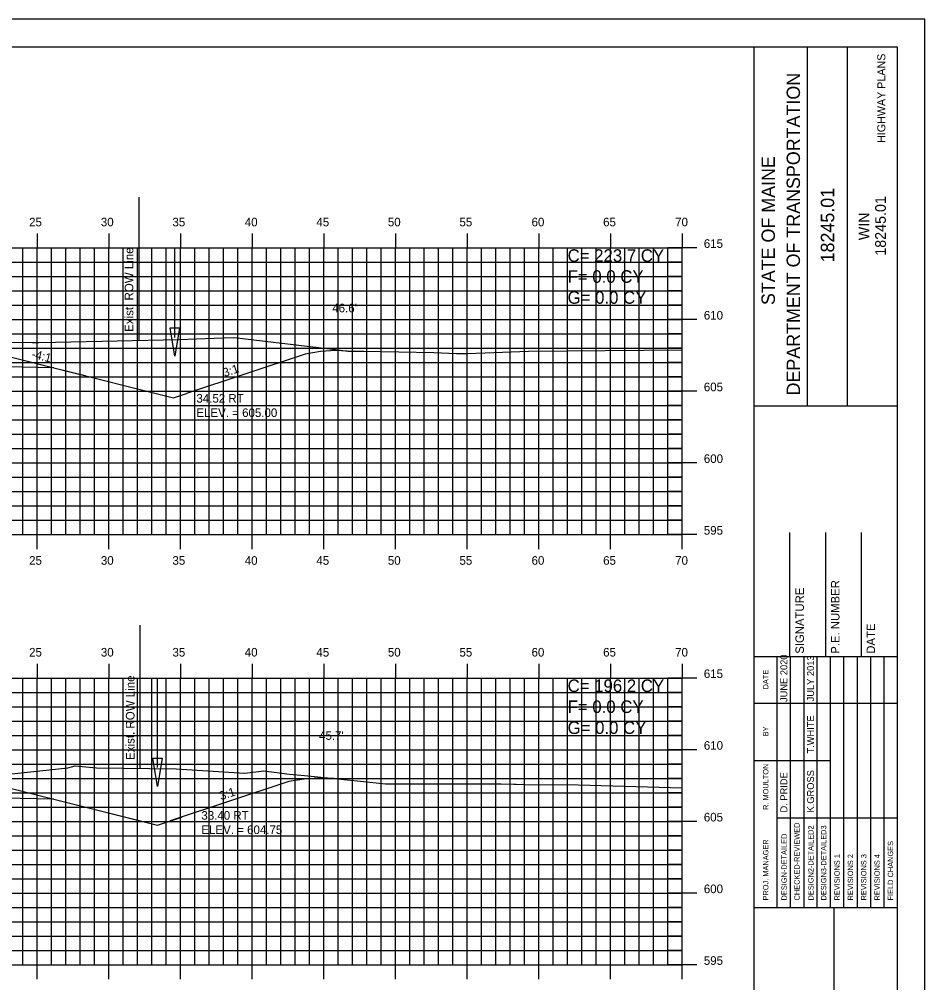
# Model space of a CAD drawing. Extents: x 1070760 to 1070930, y 779716 to 779826.
# Drawn here: x 1070866.6 to 1070929.8, y 779758.5 to 779825.6 of the extents above; entities that cross this region are included whole.
import ezdxf

# ---------------------------------------------------------------- set-up
doc = ezdxf.new("R2010")
doc.units = 0
for name, color, linetype in [('ANNOTATION', 7, 'Continuous'), ('BORDER', 7, 'Continuous'), ('D_Drainage_Ditch_Line', 7, 'Continuous'), ('D_Roadway_Centerline', 7, 'Continuous'), ('D_Roadway_Drive_SubGrade', 7, 'Continuous'), ('D_Roadway_SlopeLines', 7, 'Continuous'), ('D_Roadway_SubGrade', 7, 'Continuous'), ('D_Text_Standard', 7, 'Continuous'), ('E_ROW_Line', 7, 'Continuous'), ('H_V ANNOTATION', 7, 'Continuous'), ('HIGHWAY_TITLE', 7, 'Continuous'), ('MAJOR', 7, 'Continuous'), ('MINOR', 7, 'Continuous'), ('PLOT BOUNDARY', 7, 'Continuous'), ('S_Roadway_Centerline', 7, 'Continuous')]:
    doc.layers.add(name, color=color, linetype=linetype)

msp = doc.modelspace()

# ---------------------------------------------------------------- linework, layer by layer
at = {"layer": 'BORDER'}
for p, q in [((1070917.881, 779718.706), (1070917.881, 779823.706)), ((1070921.609, 779798.703), (1070921.609, 779823.703)), ((1070924.404, 779798.703), (1070924.404, 779823.703)), ((1070917.882, 779798.7), (1070927.881, 779798.7)), ((1070920.381, 779781.209), (1070920.381, 779789.856)), ((1070922.881, 779781.209), (1070922.881, 779789.856)), ((1070925.381, 779781.209), (1070925.381, 779789.856)), ((1070917.881, 779781.209), (1070927.881, 779781.209)), ((1070917.881, 779763.709), (1070927.881, 779763.709)), ((1070923.472, 779728.709), (1070923.472, 779763.709))]:
    msp.add_line(p, q, dxfattribs=at)
msp.add_lwpolyline([(1070767.881, 779718.706), (1070927.881, 779718.706), (1070927.881, 779823.706), (1070767.881, 779823.706)], close=True, dxfattribs=at)
for points in [[(1070919.496, 779777.959), (1070919.496, 779781.209)], [(1070920.428, 779763.712), (1070920.428, 779781.209)], [(1070921.36, 779781.209), (1070921.36, 779763.712)], [(1070922.292, 779763.712), (1070922.292, 779781.209)], [(1070923.223, 779763.712), (1070923.223, 779781.209)], [(1070924.155, 779763.712), (1070924.155, 779781.209)], [(1070925.087, 779763.712), (1070925.087, 779781.209)], [(1070926.018, 779763.712), (1070926.018, 779781.209)], [(1070926.95, 779763.712), (1070926.95, 779781.209)], [(1070919.497, 779763.712), (1070919.497, 779780.503)], [(1070917.881, 779777.959), (1070927.881, 779777.959)], [(1070917.881, 779773.959), (1070919.497, 779773.959)], [(1070919.496, 779773.959), (1070923.222, 779773.959)], [(1070919.496, 779769.959), (1070927.881, 779769.959)]]:
    msp.add_lwpolyline(points, dxfattribs=at)
at = {"layer": 'D_Drainage_Ditch_Line'}
for p, q in [((1070877.484, 779803.462), (1070877.485, 779809.706)), ((1070876.282, 779773.462), (1070876.283, 779779.706))]:
    msp.add_line(p, q, dxfattribs=at)
for points in [[(1070877.156, 779804.118), (1070877.812, 779804.118), (1070877.484, 779802.15)], [(1070875.954, 779774.118), (1070876.61, 779774.118), (1070876.282, 779772.15)]]:
    msp.add_lwpolyline(points, close=True, dxfattribs=at)
at = {"layer": 'D_Roadway_Centerline'}
for points in [[(1070889.505, 779802.511), (1070888.699, 779802.539), (1070887.647, 779802.467), (1070886.589, 779802.291), (1070878.304, 779799.553)], [(1070888.58, 779772.696), (1070887.556, 779772.732), (1070886.505, 779772.659), (1070885.447, 779772.483), (1070877.161, 779769.746)], [(1070869.04, 779771.266), (1070875.281, 779769.706)]]:
    msp.add_lwpolyline(points, dxfattribs=at)
at = {"layer": 'D_Roadway_Drive_SubGrade'}
for p, q in [((1070869.04, 779801.347), (1070877.404, 779799.256)), ((1070877.404, 779799.256), (1070878.304, 779799.553)), ((1070869.04, 779771.266), (1070876.283, 779769.456)), ((1070876.283, 779769.456), (1070877.977, 779770.016))]:
    msp.add_line(p, q, dxfattribs=at)
at = {"layer": 'D_Roadway_SlopeLines'}
for points in [[(1070869.04, 779801.347), (1070871.228, 779800.799)], [(1070869.04, 779771.266), (1070875.281, 779769.706)]]:
    msp.add_lwpolyline(points, dxfattribs=at)
at = {"layer": 'D_Roadway_SubGrade'}
for points in [[(1070854.881, 779802.213), (1070854.881, 779803.713), (1070854.881, 779803.713), (1070858.881, 779803.553), (1070858.881, 779803.886), (1070869.04, 779801.347), (1070854.881, 779801.63)], [(1070854.881, 779772.133), (1070854.881, 779773.633), (1070854.881, 779773.633), (1070858.881, 779773.473), (1070858.881, 779773.806), (1070869.04, 779771.266), (1070854.881, 779771.549)]]:
    msp.add_lwpolyline(points, close=True, dxfattribs=at)
at = {"layer": 'E_ROW_Line'}
for p, q in [((1070874.993, 779803.252), (1070874.993, 779813.252)), ((1070874.993, 779803.252), (1070874.993, 779813.252)), ((1070875.075, 779773.401), (1070875.075, 779783.401)), ((1070875.075, 779773.401), (1070875.075, 779783.401))]:
    msp.add_line(p, q, dxfattribs=at)
at = {"layer": 'MAJOR'}
for p, q in [((1070867.881, 779810.708), (1070867.881, 779809.706)), ((1070872.881, 779810.708), (1070872.881, 779809.706)), ((1070877.881, 779810.708), (1070877.881, 779809.706)), ((1070882.881, 779810.708), (1070882.881, 779809.706)), ((1070887.881, 779810.708), (1070887.881, 779809.706)), ((1070892.881, 779810.708), (1070892.881, 779809.706)), ((1070897.881, 779810.708), (1070897.881, 779809.706)), ((1070902.881, 779810.708), (1070902.881, 779809.706)), ((1070907.881, 779810.708), (1070907.881, 779809.706)), ((1070912.881, 779810.708), (1070912.881, 779809.706)), ((1070772.881, 779809.706), (1070912.881, 779809.706)), ((1070772.881, 779809.706), (1070912.881, 779809.706)), ((1070867.881, 779789.706), (1070867.881, 779809.706)), ((1070872.881, 779789.706), (1070872.881, 779809.706)), ((1070877.881, 779789.706), (1070877.881, 779809.706)), ((1070882.881, 779789.706), (1070882.881, 779809.706)), ((1070887.881, 779789.706), (1070887.881, 779809.706)), ((1070892.881, 779789.706), (1070892.881, 779809.706)), ((1070897.881, 779789.706), (1070897.881, 779809.706)), ((1070902.881, 779789.706), (1070902.881, 779809.706)), ((1070907.881, 779789.706), (1070907.881, 779809.706)), ((1070913.883, 779809.706), (1070911.879, 779809.706)), ((1070912.881, 779789.706), (1070912.881, 779809.706)), ((1070912.881, 779789.706), (1070912.881, 779809.706)), ((1070772.881, 779804.706), (1070912.881, 779804.706)), ((1070913.883, 779804.706), (1070911.879, 779804.706)), ((1070772.881, 779799.706), (1070912.881, 779799.706)), ((1070913.883, 779799.706), (1070911.879, 779799.706)), ((1070772.881, 779794.706), (1070912.881, 779794.706)), ((1070913.883, 779794.706), (1070911.879, 779794.706)), ((1070772.881, 779789.706), (1070912.881, 779789.706)), ((1070772.881, 779789.706), (1070912.881, 779789.706)), ((1070867.881, 779788.704), (1070867.881, 779789.706)), ((1070872.881, 779788.704), (1070872.881, 779789.706)), ((1070877.881, 779788.704), (1070877.881, 779789.706)), ((1070882.881, 779788.704), (1070882.881, 779789.706)), ((1070887.881, 779788.704), (1070887.881, 779789.706)), ((1070892.881, 779788.704), (1070892.881, 779789.706)), ((1070897.881, 779788.704), (1070897.881, 779789.706)), ((1070902.881, 779788.704), (1070902.881, 779789.706)), ((1070907.881, 779788.704), (1070907.881, 779789.706)), ((1070913.883, 779789.706), (1070911.879, 779789.706)), ((1070912.881, 779788.704), (1070912.881, 779789.706)), ((1070867.881, 779780.708), (1070867.881, 779779.706)), ((1070872.881, 779780.708), (1070872.881, 779779.706)), ((1070877.881, 779780.708), (1070877.881, 779779.706)), ((1070882.881, 779780.708), (1070882.881, 779779.706)), ((1070887.881, 779780.708), (1070887.881, 779779.706)), ((1070892.881, 779780.708), (1070892.881, 779779.706)), ((1070897.881, 779780.708), (1070897.881, 779779.706)), ((1070902.881, 779780.708), (1070902.881, 779779.706)), ((1070907.881, 779780.708), (1070907.881, 779779.706)), ((1070912.881, 779780.708), (1070912.881, 779779.706)), ((1070772.881, 779779.706), (1070912.881, 779779.706)), ((1070772.881, 779779.706), (1070912.881, 779779.706)), ((1070867.881, 779759.706), (1070867.881, 779779.706)), ((1070872.881, 779759.706), (1070872.881, 779779.706)), ((1070877.881, 779759.706), (1070877.881, 779779.706)), ((1070882.881, 779759.706), (1070882.881, 779779.706)), ((1070887.881, 779759.706), (1070887.881, 779779.706)), ((1070892.881, 779759.706), (1070892.881, 779779.706)), ((1070897.881, 779759.706), (1070897.881, 779779.706)), ((1070902.881, 779759.706), (1070902.881, 779779.706)), ((1070907.881, 779759.706), (1070907.881, 779779.706)), ((1070913.883, 779779.706), (1070911.879, 779779.706)), ((1070912.881, 779759.706), (1070912.881, 779779.706)), ((1070912.881, 779759.706), (1070912.881, 779779.706)), ((1070772.881, 779774.706), (1070912.881, 779774.706)), ((1070913.883, 779774.706), (1070911.879, 779774.706)), ((1070772.881, 779769.706), (1070912.881, 779769.706)), ((1070913.883, 779769.706), (1070911.879, 779769.706)), ((1070772.881, 779764.706), (1070912.881, 779764.706)), ((1070913.883, 779764.706), (1070911.879, 779764.706)), ((1070772.881, 779759.706), (1070912.881, 779759.706)), ((1070772.881, 779759.706), (1070912.881, 779759.706)), ((1070867.881, 779758.704), (1070867.881, 779759.706)), ((1070872.881, 779758.704), (1070872.881, 779759.706)), ((1070877.881, 779758.704), (1070877.881, 779759.706)), ((1070882.881, 779758.704), (1070882.881, 779759.706)), ((1070887.881, 779758.704), (1070887.881, 779759.706)), ((1070892.881, 779758.704), (1070892.881, 779759.706)), ((1070897.881, 779758.704), (1070897.881, 779759.706)), ((1070902.881, 779758.704), (1070902.881, 779759.706)), ((1070907.881, 779758.704), (1070907.881, 779759.706)), ((1070913.883, 779759.706), (1070911.879, 779759.706)), ((1070912.881, 779758.704), (1070912.881, 779759.706))]:
    msp.add_line(p, q, dxfattribs=at)
at = {"layer": 'MINOR'}
for p, q in [((1070866.881, 779789.706), (1070866.881, 779809.706)), ((1070868.881, 779789.706), (1070868.881, 779809.706)), ((1070869.881, 779789.706), (1070869.881, 779809.706)), ((1070870.881, 779789.706), (1070870.881, 779809.706)), ((1070871.881, 779789.706), (1070871.881, 779809.706)), ((1070873.881, 779789.706), (1070873.881, 779809.706)), ((1070874.881, 779789.706), (1070874.881, 779809.706)), ((1070875.881, 779789.706), (1070875.881, 779809.706)), ((1070876.881, 779789.706), (1070876.881, 779809.706)), ((1070878.881, 779789.706), (1070878.881, 779809.706)), ((1070879.881, 779789.706), (1070879.881, 779809.706)), ((1070880.881, 779789.706), (1070880.881, 779809.706)), ((1070881.881, 779789.706), (1070881.881, 779809.706)), ((1070883.881, 779789.706), (1070883.881, 779809.706)), ((1070884.881, 779789.706), (1070884.881, 779809.706)), ((1070885.881, 779789.706), (1070885.881, 779809.706)), ((1070886.881, 779789.706), (1070886.881, 779809.706)), ((1070888.881, 779789.706), (1070888.881, 779809.706)), ((1070889.881, 779789.706), (1070889.881, 779809.706)), ((1070890.881, 779789.706), (1070890.881, 779809.706)), ((1070891.881, 779789.706), (1070891.881, 779809.706)), ((1070893.881, 779789.706), (1070893.881, 779809.706)), ((1070894.881, 779789.706), (1070894.881, 779809.706)), ((1070895.881, 779789.706), (1070895.881, 779809.706)), ((1070896.881, 779789.706), (1070896.881, 779809.706)), ((1070898.881, 779789.706), (1070898.881, 779809.706)), ((1070899.881, 779789.706), (1070899.881, 779809.706)), ((1070900.881, 779789.706), (1070900.881, 779809.706)), ((1070901.881, 779789.706), (1070901.881, 779809.706)), ((1070903.881, 779789.706), (1070903.881, 779809.706)), ((1070904.881, 779789.706), (1070904.881, 779809.706)), ((1070905.881, 779789.706), (1070905.881, 779809.706)), ((1070906.881, 779789.706), (1070906.881, 779809.706)), ((1070908.881, 779789.706), (1070908.881, 779809.706)), ((1070909.881, 779789.706), (1070909.881, 779809.706)), ((1070910.881, 779789.706), (1070910.881, 779809.706)), ((1070911.881, 779789.706), (1070911.881, 779809.706)), ((1070772.881, 779808.706), (1070912.881, 779808.706)), ((1070912.881, 779808.706), (1070911.879, 779808.706)), ((1070772.881, 779807.706), (1070912.881, 779807.706)), ((1070912.881, 779807.706), (1070911.879, 779807.706)), ((1070772.881, 779806.706), (1070912.881, 779806.706)), ((1070912.881, 779806.706), (1070911.879, 779806.706)), ((1070772.881, 779805.706), (1070912.881, 779805.706)), ((1070912.881, 779805.706), (1070911.879, 779805.706)), ((1070772.881, 779803.706), (1070912.881, 779803.706)), ((1070912.881, 779803.706), (1070911.879, 779803.706)), ((1070772.881, 779802.706), (1070912.881, 779802.706)), ((1070912.881, 779802.706), (1070911.879, 779802.706)), ((1070772.881, 779801.706), (1070912.881, 779801.706)), ((1070912.881, 779801.706), (1070911.879, 779801.706)), ((1070772.881, 779800.706), (1070912.881, 779800.706)), ((1070912.881, 779800.706), (1070911.879, 779800.706)), ((1070772.881, 779798.706), (1070912.881, 779798.706)), ((1070912.881, 779798.706), (1070911.879, 779798.706)), ((1070772.881, 779797.706), (1070912.881, 779797.706)), ((1070912.881, 779797.706), (1070911.879, 779797.706)), ((1070772.881, 779796.706), (1070912.881, 779796.706)), ((1070912.881, 779796.706), (1070911.879, 779796.706)), ((1070772.881, 779795.706), (1070912.881, 779795.706)), ((1070912.881, 779795.706), (1070911.879, 779795.706)), ((1070772.881, 779793.706), (1070912.881, 779793.706)), ((1070912.881, 779793.706), (1070911.879, 779793.706)), ((1070772.881, 779792.706), (1070912.881, 779792.706)), ((1070912.881, 779792.706), (1070911.879, 779792.706)), ((1070772.881, 779791.706), (1070912.881, 779791.706)), ((1070912.881, 779791.706), (1070911.879, 779791.706)), ((1070772.881, 779790.706), (1070912.881, 779790.706)), ((1070912.881, 779790.706), (1070911.879, 779790.706)), ((1070866.881, 779759.706), (1070866.881, 779779.706)), ((1070868.881, 779759.706), (1070868.881, 779779.706)), ((1070869.881, 779759.706), (1070869.881, 779779.706)), ((1070870.881, 779759.706), (1070870.881, 779779.706)), ((1070871.881, 779759.706), (1070871.881, 779779.706)), ((1070873.881, 779759.706), (1070873.881, 779779.706)), ((1070874.881, 779759.706), (1070874.881, 779779.706)), ((1070875.881, 779759.706), (1070875.881, 779779.706)), ((1070876.881, 779759.706), (1070876.881, 779779.706)), ((1070878.881, 779759.706), (1070878.881, 779779.706)), ((1070879.881, 779759.706), (1070879.881, 779779.706)), ((1070880.881, 779759.706), (1070880.881, 779779.706)), ((1070881.881, 779759.706), (1070881.881, 779779.706)), ((1070883.881, 779759.706), (1070883.881, 779779.706)), ((1070884.881, 779759.706), (1070884.881, 779779.706)), ((1070885.881, 779759.706), (1070885.881, 779779.706)), ((1070886.881, 779759.706), (1070886.881, 779779.706)), ((1070888.881, 779759.706), (1070888.881, 779779.706)), ((1070889.881, 779759.706), (1070889.881, 779779.706)), ((1070890.881, 779759.706), (1070890.881, 779779.706)), ((1070891.881, 779759.706), (1070891.881, 779779.706)), ((1070893.881, 779759.706), (1070893.881, 779779.706)), ((1070894.881, 779759.706), (1070894.881, 779779.706)), ((1070895.881, 779759.706), (1070895.881, 779779.706)), ((1070896.881, 779759.706), (1070896.881, 779779.706)), ((1070898.881, 779759.706), (1070898.881, 779779.706)), ((1070899.881, 779759.706), (1070899.881, 779779.706)), ((1070900.881, 779759.706), (1070900.881, 779779.706)), ((1070901.881, 779759.706), (1070901.881, 779779.706)), ((1070903.881, 779759.706), (1070903.881, 779779.706)), ((1070904.881, 779759.706), (1070904.881, 779779.706)), ((1070905.881, 779759.706), (1070905.881, 779779.706)), ((1070906.881, 779759.706), (1070906.881, 779779.706)), ((1070908.881, 779759.706), (1070908.881, 779779.706)), ((1070909.881, 779759.706), (1070909.881, 779779.706)), ((1070910.881, 779759.706), (1070910.881, 779779.706)), ((1070911.881, 779759.706), (1070911.881, 779779.706)), ((1070772.881, 779778.706), (1070912.881, 779778.706)), ((1070912.881, 779778.706), (1070911.879, 779778.706)), ((1070772.881, 779777.706), (1070912.881, 779777.706)), ((1070912.881, 779777.706), (1070911.879, 779777.706)), ((1070772.881, 779776.706), (1070912.881, 779776.706)), ((1070912.881, 779776.706), (1070911.879, 779776.706)), ((1070772.881, 779775.706), (1070912.881, 779775.706)), ((1070912.881, 779775.706), (1070911.879, 779775.706)), ((1070772.881, 779773.706), (1070912.881, 779773.706)), ((1070912.881, 779773.706), (1070911.879, 779773.706)), ((1070772.881, 779772.706), (1070912.881, 779772.706)), ((1070912.881, 779772.706), (1070911.879, 779772.706)), ((1070772.881, 779771.706), (1070912.881, 779771.706)), ((1070912.881, 779771.706), (1070911.879, 779771.706)), ((1070772.881, 779770.706), (1070912.881, 779770.706)), ((1070912.881, 779770.706), (1070911.879, 779770.706)), ((1070772.881, 779768.706), (1070912.881, 779768.706)), ((1070912.881, 779768.706), (1070911.879, 779768.706)), ((1070772.881, 779767.706), (1070912.881, 779767.706)), ((1070912.881, 779767.706), (1070911.879, 779767.706)), ((1070772.881, 779766.706), (1070912.881, 779766.706)), ((1070912.881, 779766.706), (1070911.879, 779766.706)), ((1070772.881, 779765.706), (1070912.881, 779765.706)), ((1070912.881, 779765.706), (1070911.879, 779765.706)), ((1070772.881, 779763.706), (1070912.881, 779763.706)), ((1070912.881, 779763.706), (1070911.879, 779763.706)), ((1070772.881, 779762.706), (1070912.881, 779762.706)), ((1070912.881, 779762.706), (1070911.879, 779762.706)), ((1070772.881, 779761.706), (1070912.881, 779761.706)), ((1070912.881, 779761.706), (1070911.879, 779761.706)), ((1070772.881, 779760.706), (1070912.881, 779760.706)), ((1070912.881, 779760.706), (1070911.879, 779760.706))]:
    msp.add_line(p, q, dxfattribs=at)
at = {"layer": 'PLOT BOUNDARY'}
msp.add_lwpolyline([(1070759.787, 779715.646), (1070929.787, 779715.646), (1070929.787, 779825.646), (1070759.787, 779825.646)], close=True, dxfattribs=at)
at = {"layer": 'S_Roadway_Centerline'}
for points in [[(1070858.356, 779803.244), (1070867.532, 779803.1), (1070867.532, 779803.1), (1070868.013, 779803.098), (1070869.164, 779803.123), (1070877.763, 779803.314), (1070880.221, 779803.417), (1070881.622, 779803.447), (1070888.882, 779802.588), (1070889.561, 779802.504), (1070890.172, 779802.502), (1070890.671, 779802.49), (1070895.551, 779802.41), (1070897.136, 779802.347), (1070897.859, 779802.343), (1070899.138, 779802.395), (1070902.143, 779802.491), (1070912.881, 779802.583)], [(1070865.676, 779772.98), (1070870.023, 779773.443), (1070870.533, 779773.581), (1070872.016, 779773.44), (1070877.58, 779773.369), (1070882.36, 779773.08), (1070883.703, 779773.23), (1070885.474, 779772.993), (1070886.537, 779772.901), (1070890.43, 779772.511), (1070892.185, 779772.332), (1070899.36, 779772.318), (1070900.245, 779772.318), (1070901.134, 779772.305), (1070901.283, 779772.295), (1070901.839, 779772.287), (1070905.609, 779772.258), (1070912.881, 779772.061)]]:
    msp.add_lwpolyline(points, dxfattribs=at)

# ---------------------------------------------------------------- texts
at = {"layer": 'ANNOTATION'}
for s, rotation, p in [('-4:1', 345.96376, (1070867.455, 779802.044)), ('3:1', 18.45931, (1070880.953, 779800.69)), ('3:1', 18.45931, (1070880.711, 779771.18))]:
    msp.add_text(s, height=0.6, rotation=rotation, dxfattribs=at).set_placement(p)
for s, p in [('34.52 RT', (1070878.992, 779798.913)), ('ELEV. = 605.00', (1070878.992, 779797.911)), ('33.40 RT', (1070879.34, 779769.828)), ('ELEV. = 604.75', (1070879.34, 779768.826))]:
    msp.add_text(s, height=0.6, dxfattribs=at).set_placement(p)
at = {"layer": 'BORDER'}
for s, height, p in [('DEPARTMENT OF TRANSPORTATION', 0.93176, (1070921.088, 779799.412)), ('DEPARTMENT OF TRANSPORTATION', 0.93176, (1070921.088, 779799.412)), ('STATE OF MAINE', 0.93176, (1070919.336, 779805.718)), ('STATE OF MAINE', 0.93176, (1070919.336, 779805.718)), ('18245.01', 0.9318, (1070923.473, 779808.691)), ('18245.01', 0.7453, (1070927.076, 779809.156)), ('WIN', 0.7453, (1070925.918, 779810.236)), ('P.E. NUMBER', 0.59055, (1070923.842, 779781.401)), ('SIGNATURE', 0.5906, (1070921.361, 779781.401)), ('DATE', 0.5906, (1070926.322, 779781.401)), ('JUNE 2020', 0.4845, (1070920.204, 779778.034)), ('JULY 2013', 0.4845, (1070922.067, 779778.08)), ('DATE', 0.3714, (1070918.885, 779778.914)), ('T.WHITE', 0.4845, (1070922.067, 779774.444)), ('BY', 0.3714, (1070918.885, 779775.644)), ('R. MOULTON', 0.3727, (1070918.885, 779770.511)), ('D. PRIDE', 0.4845, (1070920.204, 779770.332)), ('K.GROSS', 0.4845, (1070922.067, 779770.332)), ('CHECKED-REVIEWED', 0.37275, (1070921.062, 779764.197)), ('DESIGN2-DETAILED2', 0.37275, (1070922.031, 779764.197)), ('DESIGN3-DETAILED3', 0.37275, (1070922.925, 779764.197)), ('PROJ. MANAGER', 0.37275, (1070918.885, 779764.197)), ('DESIGN-DETAILED', 0.37275, (1070920.167, 779764.197)), ('FIELD CHANGES', 0.37275, (1070927.584, 779764.197)), ('REVISIONS 1', 0.37275, (1070923.857, 779764.197)), ('REVISIONS 2', 0.37275, (1070924.789, 779764.197)), ('REVISIONS 3', 0.37275, (1070925.72, 779764.197)), ('REVISIONS 4', 0.37275, (1070926.652, 779764.197))]:
    msp.add_text(s, height=height, rotation=90, dxfattribs=at).set_placement(p)
at = {"layer": 'D_Text_Standard'}
for s, p in [("46.6'", (1070888.469, 779805.211)), ("45.7'", (1070887.545, 779775.396))]:
    msp.add_text(s, height=0.6, dxfattribs=at).set_placement(p)
at = {"layer": 'E_ROW_Line'}
for p in [(1070874.593, 779803.852), (1070874.675, 779774.001)]:
    msp.add_text('Exist. ROW Line', height=0.6, rotation=90, dxfattribs=at).set_placement(p)
at = {"layer": 'H_V ANNOTATION'}
for s, height, p in [('25', 0.6, (1070867.327, 779811.206)), ('30', 0.6, (1070872.329, 779811.206)), ('35', 0.6, (1070877.321, 779811.206)), ('40', 0.6, (1070882.367, 779811.206)), ('45', 0.6, (1070887.359, 779811.206)), ('50', 0.6, (1070892.345, 779811.206)), ('55', 0.6, (1070897.337, 779811.206)), ('60', 0.6, (1070902.367, 779811.206)), ('65', 0.6, (1070907.359, 779811.206)), ('70', 0.6, (1070912.383, 779811.206)), ('615', 0.6, (1070914.381, 779809.706)), ('C= 223.7 CY', 0.87498, (1070904.881, 779808.731)), ('F= 0.0 CY', 0.875, (1070904.881, 779807.269)), ('G= 0.0 CY', 0.875, (1070904.881, 779805.808)), ('610', 0.6, (1070914.381, 779804.706)), ('605', 0.6, (1070914.381, 779799.706)), ('600', 0.6, (1070914.381, 779794.706)), ('595', 0.6, (1070914.381, 779789.706)), ('25', 0.6, (1070867.327, 779787.606)), ('30', 0.6, (1070872.329, 779787.606)), ('35', 0.6, (1070877.321, 779787.606)), ('40', 0.6, (1070882.367, 779787.606)), ('45', 0.6, (1070887.359, 779787.606)), ('50', 0.6, (1070892.345, 779787.606)), ('55', 0.6, (1070897.337, 779787.606)), ('60', 0.6, (1070902.367, 779787.606)), ('65', 0.6, (1070907.359, 779787.606)), ('70', 0.6, (1070912.383, 779787.606)), ('25', 0.6, (1070867.327, 779781.206)), ('30', 0.6, (1070872.329, 779781.206)), ('35', 0.6, (1070877.321, 779781.206)), ('40', 0.6, (1070882.367, 779781.206)), ('45', 0.6, (1070887.359, 779781.206)), ('50', 0.6, (1070892.345, 779781.206)), ('55', 0.6, (1070897.337, 779781.206)), ('60', 0.6, (1070902.367, 779781.206)), ('65', 0.6, (1070907.359, 779781.206)), ('70', 0.6, (1070912.383, 779781.206)), ('615', 0.6, (1070914.381, 779779.706)), ('C= 196.2 CY', 0.87498, (1070904.881, 779778.731)), ('F= 0.0 CY', 0.875, (1070904.881, 779777.269)), ('G= 0.0 CY', 0.875, (1070904.881, 779775.808)), ('610', 0.6, (1070914.381, 779774.706)), ('605', 0.6, (1070914.381, 779769.706)), ('600', 0.6, (1070914.381, 779764.706)), ('595', 0.6, (1070914.381, 779759.706))]:
    msp.add_text(s, height=height, dxfattribs=at).set_placement(p)
at = {"layer": 'HIGHWAY_TITLE'}
msp.add_text('HIGHWAY PLANS', height=0.55901, rotation=90, dxfattribs=at).set_placement((1070927.039, 779817.021))

doc.saveas('drawing.dxf')
